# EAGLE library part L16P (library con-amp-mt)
AMP MT CONNECTOR
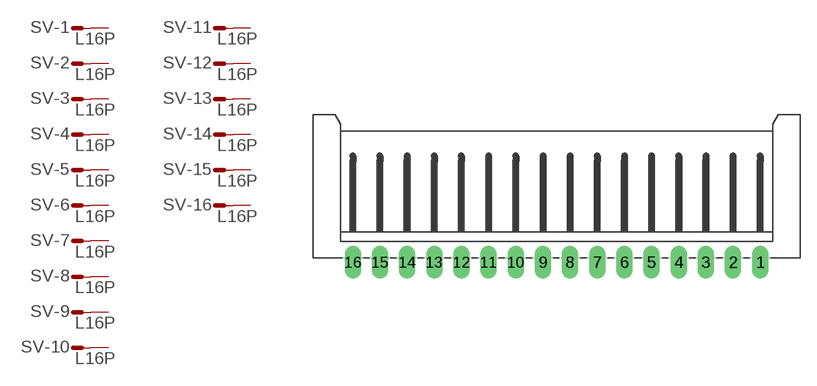
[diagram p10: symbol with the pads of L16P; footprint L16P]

Designator prefix SV; gates -1=M -2=M -3=M -4=M -5=M -6=M -7=M -8=M -9=M -10=M -11=M -12=M -13=M -14=M -15=M -16=M

## L16P (OC_FARNELL: unknown; OC_NEWARK: unknown)  [L16P]
1  -1:S  pas
2  -2:S  pas
3  -3:S  pas
4  -4:S  pas
5  -5:S  pas
6  -6:S  pas
7  -7:S  pas
8  -8:S  pas
9  -9:S  pas
10  -10:S  pas
11  -11:S  pas
12  -12:S  pas
13  -13:S  pas
14  -14:S  pas
15  -15:S  pas
16  -16:S  pas

## Footprint L16P (pad centres in mm)
AMP MT CONNECTOR
drill 1.016 long: 1 18.75,-6.25; 2 16.25,-6.25; 3 13.75,-6.25; 4 11.25,-6.25; 5 8.75,-6.25; 6 6.25,-6.25; 7 3.75,-6.25; 8 1.25,-6.25; 9 -1.25,-6.25; 10 -3.75,-6.25; 11 -6.25,-6.25; 12 -8.75,-6.25; 13 -11.25,-6.25; 14 -13.75,-6.25; 15 -16.25,-6.25; 16 -18.74,-6.25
